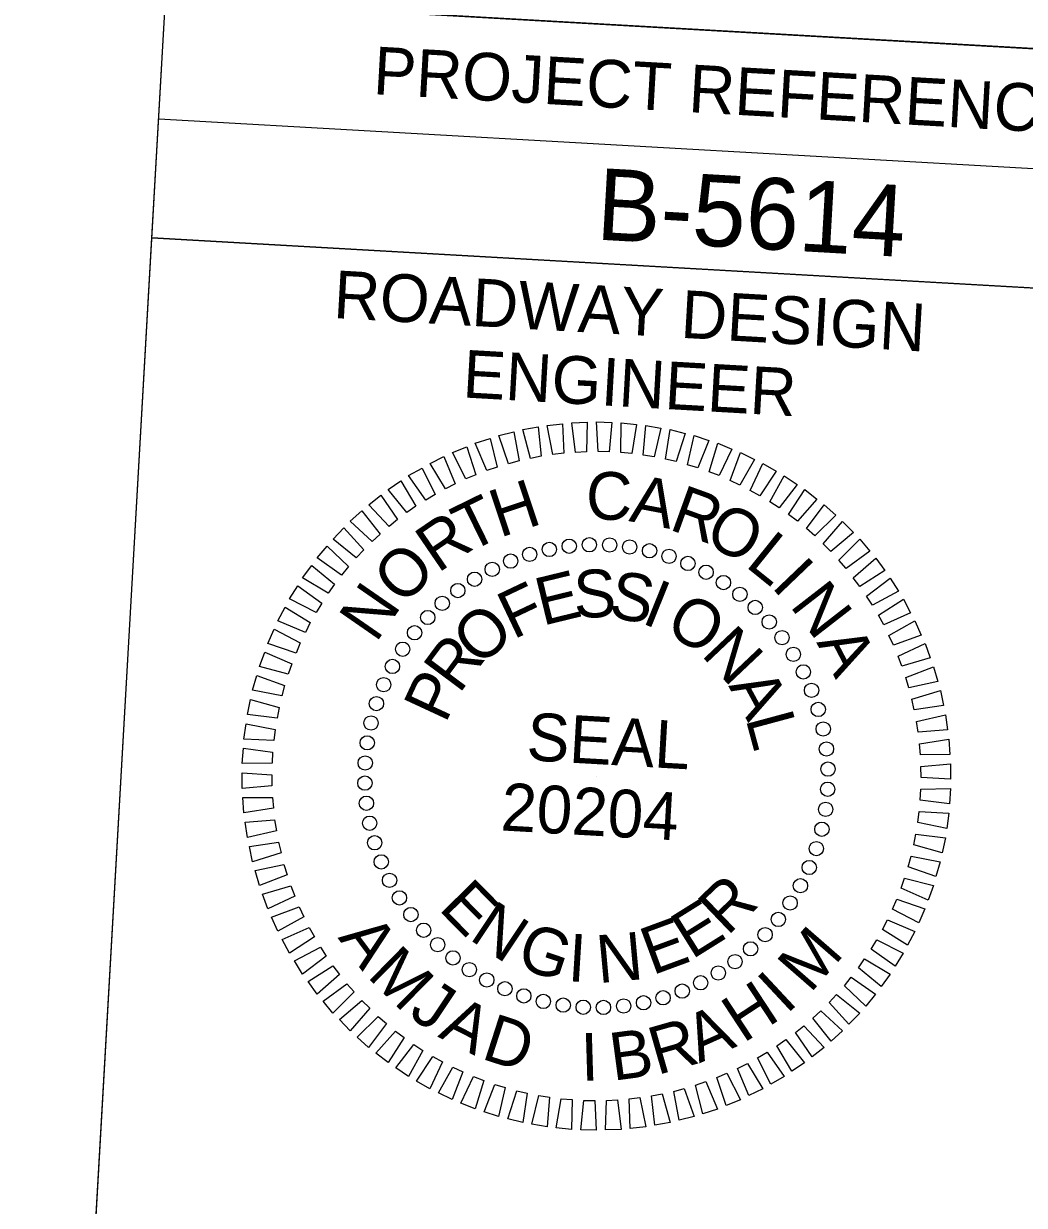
# Model space of a CAD drawing. Extents: x 2604316 to 2606605, y 617090 to 619543.
# Drawn here: x 2605834.5 to 2605939.3, y 618872.2 to 618996 of the extents above; entities that cross this region are included whole.
import ezdxf

# ---------------------------------------------------------------- set-up
doc = ezdxf.new("R2010")
doc.units = 0
for name, color, linetype in [('Default', 7, 'Continuous'), ('Scratch_Level_1', 7, 'Continuous'), ('Sheet Data Field CELL', 7, 'Continuous'), ('Sheet PE Seal Cell', 7, 'Continuous'), ('Sheet Plan And Profile CELL', 7, 'Continuous')]:
    doc.layers.add(name, color=color, linetype=linetype)

msp = doc.modelspace()

# ---------------------------------------------------------------- linework, layer by layer
at = {"layer": 'Scratch_Level_1'}
msp.add_lwpolyline([(2606037.66, 618786.46), (2605837.94, 618797.83), (2605849.36, 618998.56), (2604589.3, 619070.32), (2604537.44, 618159.71), (2605997.22, 618076.57)], close=True, dxfattribs=at)
msp.add_lwpolyline([(2606037.66, 618786.46), (2605837.94, 618797.83), (2605849.36, 618998.56), (2604589.3, 619070.32), (2604537.44, 618159.71), (2605997.22, 618076.57)], close=True, dxfattribs=at)
at = {"layer": 'Sheet PE Seal Cell'}
msp.add_line((2605894.48, 618917.17), (2605894.48, 618917.17), dxfattribs=at)
for points in [[(2605889.92, 618950.85), (2605889.32, 618953.91), (2605890.93, 618954.07), (2605891.06, 618950.99)], [(2605892.29, 618951.08), (2605891.9, 618954.18), (2605893.52, 618954.23), (2605893.43, 618951.15)], [(2605894.66, 618951.16), (2605894.49, 618954.27), (2605896.1, 618954.21), (2605895.8, 618951.14)], [(2605897.03, 618951.06), (2605897.08, 618954.18), (2605898.68, 618954), (2605898.17, 618950.96)], [(2605899.39, 618950.8), (2605899.65, 618953.91), (2605901.24, 618953.62), (2605900.51, 618950.62)], [(2605885.28, 618949.89), (2605884.26, 618952.84), (2605885.83, 618953.22), (2605886.38, 618950.19)], [(2605887.59, 618950.45), (2605886.77, 618953.46), (2605888.37, 618953.74), (2605888.71, 618950.67)], [(2605901.72, 618950.38), (2605902.2, 618953.46), (2605903.77, 618953.06), (2605902.83, 618950.12)], [(2605904.02, 618949.79), (2605904.72, 618952.83), (2605906.25, 618952.32), (2605905.11, 618949.46)], [(2605880.82, 618948.29), (2605879.4, 618951.07), (2605880.9, 618951.67), (2605881.87, 618948.74)], [(2605883.02, 618949.17), (2605881.8, 618952.04), (2605883.34, 618952.53), (2605884.1, 618949.54)], [(2605906.27, 618949.04), (2605907.18, 618952.03), (2605908.67, 618951.42), (2605907.34, 618948.64)], [(2605878.68, 618947.26), (2605877.07, 618949.93), (2605878.52, 618950.63), (2605879.7, 618947.78)], [(2605908.47, 618948.14), (2605909.58, 618951.06), (2605911.03, 618950.34), (2605909.5, 618947.66)], [(2605876.62, 618946.08), (2605874.82, 618948.64), (2605876.23, 618949.44), (2605877.6, 618946.67)], [(2605910.59, 618947.09), (2605911.91, 618949.92), (2605913.3, 618949.11), (2605911.59, 618946.54)], [(2605874.64, 618944.77), (2605872.68, 618947.19), (2605874.02, 618948.09), (2605875.58, 618945.43)], [(2605912.64, 618945.9), (2605914.15, 618948.63), (2605915.49, 618947.72), (2605913.6, 618945.28)], [(2605872.77, 618943.32), (2605870.64, 618945.6), (2605871.91, 618946.58), (2605873.65, 618944.04)], [(2605914.6, 618944.56), (2605916.3, 618947.18), (2605917.57, 618946.18), (2605915.52, 618943.87)], [(2605916.46, 618943.09), (2605918.34, 618945.58), (2605919.53, 618944.5), (2605917.33, 618942.34)], [(2605871, 618941.74), (2605868.71, 618943.86), (2605869.92, 618944.94), (2605871.83, 618942.52)], [(2605869.34, 618940.04), (2605866.91, 618942), (2605868.04, 618943.16), (2605870.12, 618940.88)], [(2605918.22, 618941.49), (2605920.26, 618943.85), (2605921.38, 618942.68), (2605919.03, 618940.69)], [(2605919.86, 618939.78), (2605922.06, 618941.99), (2605923.09, 618940.74), (2605920.61, 618938.92)], [(2605867.8, 618938.23), (2605865.24, 618940.02), (2605866.29, 618941.25), (2605868.52, 618939.12)], [(2605866.4, 618936.32), (2605863.72, 618937.92), (2605864.68, 618939.23), (2605867.05, 618937.26)], [(2605921.37, 618937.95), (2605923.73, 618940), (2605924.67, 618938.69), (2605922.06, 618937.04)], [(2605922.76, 618936.03), (2605925.25, 618937.91), (2605926.1, 618936.53), (2605923.38, 618935.07)], [(2605865.13, 618934.31), (2605862.35, 618935.73), (2605863.21, 618937.09), (2605865.72, 618935.29)], [(2605924, 618934.01), (2605926.62, 618935.71), (2605927.37, 618934.28), (2605924.56, 618933.01)], [(2605864.01, 618932.22), (2605861.13, 618933.44), (2605861.9, 618934.86), (2605864.52, 618933.24)], [(2605925.11, 618931.91), (2605927.83, 618933.42), (2605928.48, 618931.94), (2605925.59, 618930.87)], [(2605863.03, 618930.06), (2605860.08, 618931.07), (2605860.74, 618932.55), (2605863.48, 618931.11)], [(2605926.06, 618929.73), (2605928.89, 618931.06), (2605929.43, 618929.54), (2605926.47, 618928.67)], [(2605862.21, 618927.84), (2605859.19, 618928.64), (2605859.75, 618930.16), (2605862.58, 618928.92)], [(2605926.86, 618927.5), (2605929.77, 618928.62), (2605930.21, 618927.07), (2605927.2, 618926.41)], [(2605861.54, 618925.56), (2605858.48, 618926.15), (2605858.93, 618927.7), (2605861.84, 618926.66)], [(2605927.5, 618925.22), (2605930.49, 618926.13), (2605930.81, 618924.55), (2605927.76, 618924.1)], [(2605861.04, 618923.24), (2605857.94, 618923.62), (2605858.28, 618925.2), (2605861.25, 618924.36)], [(2605927.98, 618922.89), (2605931.02, 618923.6), (2605931.24, 618922), (2605928.17, 618921.76)], [(2605860.69, 618920.89), (2605857.58, 618921.05), (2605857.81, 618922.65), (2605860.83, 618922.03)], [(2605928.3, 618920.54), (2605931.38, 618921.03), (2605931.49, 618919.42), (2605928.4, 618919.4)], [(2605860.52, 618918.53), (2605857.4, 618918.47), (2605857.52, 618920.08), (2605860.57, 618919.67)], [(2605928.46, 618918.17), (2605931.56, 618918.45), (2605931.56, 618916.83), (2605928.48, 618917.03)], [(2605860.5, 618916.16), (2605857.4, 618915.88), (2605857.4, 618917.5), (2605860.48, 618917.3)], [(2605928.44, 618915.8), (2605931.56, 618915.86), (2605931.44, 618914.25), (2605928.39, 618914.66)], [(2605860.66, 618913.79), (2605857.58, 618913.3), (2605857.47, 618914.91), (2605860.56, 618914.93)], [(2605928.27, 618913.44), (2605931.38, 618913.28), (2605931.15, 618911.68), (2605928.13, 618912.3)], [(2605860.98, 618911.44), (2605857.94, 618910.73), (2605857.72, 618912.33), (2605860.79, 618912.57)], [(2605927.92, 618911.09), (2605931.02, 618910.71), (2605930.68, 618909.13), (2605927.71, 618909.97)], [(2605861.46, 618909.11), (2605858.47, 618908.2), (2605858.15, 618909.78), (2605861.2, 618910.23)], [(2605927.42, 618908.77), (2605930.48, 618908.18), (2605930.03, 618906.63), (2605927.12, 618907.67)], [(2605862.1, 618906.83), (2605859.19, 618905.71), (2605858.75, 618907.26), (2605861.76, 618907.92)], [(2605862.9, 618904.6), (2605860.07, 618903.27), (2605859.53, 618904.79), (2605862.49, 618905.66)], [(2605926.75, 618906.49), (2605929.77, 618905.69), (2605929.21, 618904.17), (2605926.38, 618905.41)], [(2605863.85, 618902.42), (2605861.12, 618900.91), (2605860.47, 618902.39), (2605863.37, 618903.46)], [(2605925.93, 618904.27), (2605928.88, 618903.26), (2605928.22, 618901.78), (2605925.48, 618903.22)], [(2605924.95, 618902.11), (2605927.83, 618900.89), (2605927.06, 618899.47), (2605924.44, 618901.09)], [(2605864.95, 618900.32), (2605862.34, 618898.62), (2605861.59, 618900.05), (2605864.4, 618901.32)], [(2605923.83, 618900.02), (2605926.61, 618898.6), (2605925.75, 618897.24), (2605923.24, 618899.04)], [(2605866.2, 618898.3), (2605863.71, 618896.42), (2605862.86, 618897.8), (2605865.58, 618899.26)], [(2605867.59, 618896.38), (2605865.23, 618894.33), (2605864.29, 618895.64), (2605866.9, 618897.29)], [(2605922.56, 618898.01), (2605925.24, 618896.41), (2605924.28, 618895.11), (2605921.91, 618897.07)], [(2605921.16, 618896.1), (2605923.71, 618894.31), (2605922.67, 618893.08), (2605920.44, 618895.21)], [(2605869.1, 618894.55), (2605866.9, 618892.34), (2605865.87, 618893.59), (2605868.35, 618895.41)], [(2605870.74, 618892.84), (2605868.7, 618890.48), (2605867.58, 618891.65), (2605869.93, 618893.64)], [(2605919.62, 618894.29), (2605922.05, 618892.33), (2605920.92, 618891.17), (2605918.84, 618893.45)], [(2605872.5, 618891.24), (2605870.62, 618888.75), (2605869.43, 618889.83), (2605871.63, 618891.99)], [(2605917.96, 618892.59), (2605920.25, 618890.47), (2605919.04, 618889.39), (2605917.13, 618891.81)], [(2605916.19, 618891.01), (2605918.32, 618888.73), (2605917.05, 618887.75), (2605915.31, 618890.29)], [(2605874.36, 618889.77), (2605872.66, 618887.15), (2605871.39, 618888.15), (2605873.44, 618890.46)], [(2605914.32, 618889.56), (2605916.28, 618887.14), (2605914.94, 618886.24), (2605913.38, 618888.91)], [(2605876.32, 618888.43), (2605874.81, 618885.7), (2605873.47, 618886.61), (2605875.36, 618889.05)], [(2605912.34, 618888.25), (2605914.14, 618885.69), (2605912.73, 618884.89), (2605911.36, 618887.66)], [(2605878.37, 618887.24), (2605877.05, 618884.41), (2605875.66, 618885.22), (2605877.37, 618887.79)], [(2605910.28, 618887.07), (2605911.89, 618884.4), (2605910.44, 618883.7), (2605909.26, 618886.55)], [(2605880.49, 618886.19), (2605879.38, 618883.27), (2605877.93, 618883.99), (2605879.46, 618886.67)], [(2605908.14, 618886.04), (2605909.56, 618883.26), (2605908.06, 618882.66), (2605907.09, 618885.59)], [(2605882.69, 618885.29), (2605881.78, 618882.3), (2605880.28, 618882.91), (2605881.62, 618885.69)], [(2605884.94, 618884.54), (2605884.24, 618881.5), (2605882.71, 618882.01), (2605883.85, 618884.87)], [(2605905.94, 618885.16), (2605907.16, 618882.29), (2605905.62, 618881.8), (2605904.86, 618884.79)], [(2605887.24, 618883.95), (2605886.76, 618880.87), (2605885.19, 618881.27), (2605886.13, 618884.21)], [(2605889.57, 618883.53), (2605889.31, 618880.42), (2605887.72, 618880.71), (2605888.44, 618883.71)], [(2605891.93, 618883.27), (2605891.88, 618880.15), (2605890.28, 618880.33), (2605890.79, 618883.37)], [(2605896.67, 618883.25), (2605897.06, 618880.15), (2605895.44, 618880.1), (2605895.53, 618883.18)], [(2605899.03, 618883.48), (2605899.64, 618880.42), (2605898.03, 618880.26), (2605897.9, 618883.34)], [(2605901.37, 618883.88), (2605902.19, 618880.87), (2605900.59, 618880.59), (2605900.25, 618883.66)], [(2605903.68, 618884.44), (2605904.7, 618881.49), (2605903.13, 618881.11), (2605902.58, 618884.14)], [(2605894.3, 618883.17), (2605894.47, 618880.06), (2605892.86, 618880.12), (2605893.16, 618883.19)]]:
    msp.add_lwpolyline(points, close=True, dxfattribs=at)
for centre in [(2605889.55, 618940.91), (2605891.63, 618941.25), (2605893.74, 618941.4), (2605895.86, 618941.38), (2605897.96, 618941.16), (2605900.04, 618940.77), (2605885.5, 618939.69), (2605887.49, 618940.39), (2605902.08, 618940.19), (2605904.06, 618939.44), (2605883.57, 618938.82), (2605905.96, 618938.52), (2605881.72, 618937.79), (2605907.78, 618937.44), (2605879.97, 618936.6), (2605909.5, 618936.21), (2605878.34, 618935.26), (2605911.1, 618934.83), (2605876.82, 618933.78), (2605912.57, 618933.31), (2605875.44, 618932.18), (2605913.91, 618931.67), (2605874.2, 618930.46), (2605915.1, 618929.92), (2605873.12, 618928.65), (2605916.14, 618928.08), (2605872.2, 618926.74), (2605917, 618926.15), (2605871.45, 618924.76), (2605917.7, 618924.15), (2605870.88, 618922.73), (2605918.22, 618922.1), (2605870.48, 618920.65), (2605918.56, 618920.01), (2605870.27, 618918.54), (2605918.72, 618917.9), (2605870.24, 618916.43), (2605918.69, 618915.79), (2605870.4, 618914.32), (2605918.48, 618913.68), (2605870.74, 618912.23), (2605918.08, 618911.6), (2605871.26, 618910.18), (2605917.51, 618909.57), (2605871.95, 618908.18), (2605916.76, 618907.59), (2605872.82, 618906.25), (2605915.84, 618905.68), (2605873.86, 618904.41), (2605914.76, 618903.87), (2605875.05, 618902.66), (2605913.52, 618902.15), (2605876.39, 618901.02), (2605912.14, 618900.55), (2605877.86, 618899.5), (2605910.62, 618899.07), (2605879.46, 618898.12), (2605908.99, 618897.73), (2605881.18, 618896.89), (2605907.24, 618896.54), (2605883, 618895.81), (2605884.9, 618894.89), (2605905.39, 618895.51), (2605886.88, 618894.14), (2605901.46, 618893.94), (2605903.46, 618894.64), (2605888.92, 618893.56), (2605891, 618893.17), (2605893.1, 618892.95), (2605895.22, 618892.93), (2605897.33, 618893.08), (2605899.41, 618893.42)]:
    msp.add_circle(centre, 0.75, dxfattribs=at)
at = {"layer": 'Sheet Plan And Profile CELL'}
msp.add_line((2605848.65, 618986.03), (2606048.37, 618974.65), dxfattribs=at)
for points in [[(2606049.09, 618987.18), (2604551.51, 619072.48), (2604491.81, 618024.18), (2605989.38, 617938.88)], [(2605849.36, 618998.56), (2606049.09, 618987.18), (2606047.66, 618962.17), (2605847.94, 618973.55)], [(2605847.94, 618973.55), (2605947.83, 618967.86), (2605941.43, 618855.53), (2605841.55, 618861.24)]]:
    msp.add_lwpolyline(points, close=True, dxfattribs=at)

# ---------------------------------------------------------------- texts
at = {"layer": 'Default'}
for s, height, p in [('ROADWAY DESIGN', 5.0001, (2605866.87, 618965.16)), ('ENGINEER', 5, (2605880.4, 618956.84))]:
    msp.add_text(s, height=height, rotation=356.7403, dxfattribs=at).set_placement(p)
at = {"layer": 'Sheet Data Field CELL'}
msp.add_text('B-5614', height=7.5, rotation=356.7403, dxfattribs=at).set_placement((2605894.36, 618973.38))
at = {"layer": 'Sheet PE Seal Cell'}
for s, rotation, p in [('C', 358.7021, (2605893.34, 618944.07)), ('H', 18.3413, (2605884.36, 618942.12)), ('A', 349.197, (2605897.8, 618943.89)), ('T', 26.1305, (2605881.07, 618940.52)), ('R', 340.1496, (2605901.96, 618943.04)), ('O', 331.9409, (2605905.58, 618941.7)), ('R', 34.3392, (2605877.87, 618938.37)), ('L', 321.2157, (2605909.95, 618939.21)), ('O', 45.0643, (2605874.22, 618934.91)), ('I', 313.7506, (2605912.68, 618937.01)), ('E', 13.7262, (2605888.83, 618932.9)), ('S', 1.964, (2605892.16, 618933.72)), ('S', 350.005, (2605895.64, 618933.84)), ('N', 55.2748, (2605871.39, 618931.04)), ('F', 25.4042, (2605885.77, 618931.43)), ('I', 338.0461, (2605899.07, 618933.24)), ('N', 307.8106, (2605914.64, 618935.02)), ('O', 329.2906, (2605901.47, 618932.35)), ('O', 41.2129, (2605882.21, 618928.52)), ('N', 313.4818, (2605905.34, 618929.87)), ('R', 53.3124, (2605880.1, 618925.69)), ('A', 297.6002, (2605917.49, 618931.17)), ('P', 65.0746, (2605878.67, 618922.58)), ('A', 298.4318, (2605908.27, 618926.62)), ('SEAL', 356.7403, (2605887.09, 618918.84)), ('L', 285.0959, (2605910.08, 618923.18)), ('20204', 356.7403, (2605884.39, 618911.48)), ('E', 314.5909, (2605877.85, 618903.23)), ('R', 43.7832, (2605908.18, 618900.34)), ('E', 32.021, (2605904.46, 618897.9)), ('N', 326.3531, (2605881.04, 618900.13)), ('E', 20.2587, (2605900.33, 618896.27)), ('A', 306.4872, (2605867.36, 618900.23)), ('G', 341.4032, (2605885.92, 618897.23)), ('I', 356.4532, (2605891.4, 618895.69)), ('N', 5.2087, (2605894.7, 618895.47)), ('M', 48.9297, (2605916.86, 618894.33)), ('M', 315.5347, (2605870.36, 618896.18)), ('H', 33.2369, (2605909.85, 618889.13)), ('I', 42.9898, (2605914.37, 618892.13)), ('J', 326.2408, (2605874.67, 618892.06)), ('A', 333.0787, (2605877.8, 618889.88)), ('D', 342.1262, (2605882.3, 618887.6)), ('A', 24.1894, (2605905.24, 618887.06)), ('B', 7.6386, (2605896.22, 618885.24)), ('R', 15.9807, (2605900.84, 618885.83)), ('I', 1.6987, (2605892.91, 618885.23))]:
    msp.add_text(s, height=5, rotation=rotation, dxfattribs=at).set_placement(p)
at = {"layer": 'Sheet Plan And Profile CELL'}
msp.add_text('PROJECT REFERENCE NO.', height=5.0001, rotation=356.7403, dxfattribs=at).set_placement((2605871.03, 618988.61))

doc.saveas('drawing.dxf')
